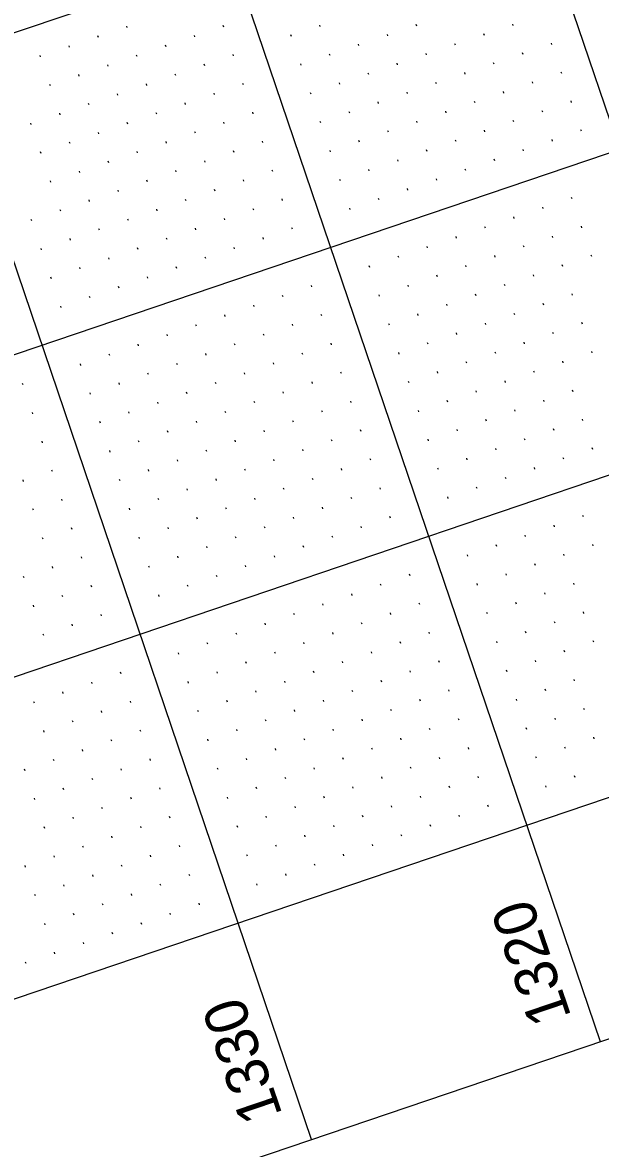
# Model space of a CAD drawing. Extents: x 2150318 to 2152065, y 143281 to 145371.
# Drawn here: x 2151453.5 to 2151548.2, y 143673.5 to 143858.1 of the extents above; entities that cross this region are included whole.
import ezdxf

# ---------------------------------------------------------------- set-up
doc = ezdxf.new("R2010")
doc.units = 0
for name, color, linetype in [('SHT_Plan_Profile_Sheet_Elev_Txt', 7, 'Continuous'), ('SHT_Profile_Grid_Major', 7, 'Continuous'), ('SHT_Profile_Grid_Minor', 7, 'Continuous'), ('SHT_Sheet_Border', 7, 'Continuous')]:
    doc.layers.add(name, color=color, linetype=linetype)

msp = doc.modelspace()

# ---------------------------------------------------------------- linework, layer by layer
at = {"layer": 'SHT_Profile_Grid_Major'}
for p, q in [((2151595.52, 143707.09), (2151089.53, 145198.6)), ((2151548.17, 143691.03), (2151042.18, 145182.54)), ((2151500.82, 143674.97), (2150994.83, 145166.47)), ((2151819.38, 143981.03), (2151345.88, 143820.4)), ((2151835.44, 143933.68), (2151361.94, 143773.05)), ((2151851.5, 143886.33), (2151378.01, 143725.7))]:
    msp.add_line(p, q, dxfattribs=at)
at = {"layer": 'SHT_Profile_Grid_Minor'}
for p, q in [((2151470.64, 143857.31), (2151470.56, 143857.55)), ((2151486.45, 143857.39), (2151486.37, 143857.63)), ((2151502.26, 143857.48), (2151502.18, 143857.71)), ((2151518.07, 143857.56), (2151517.99, 143857.8)), ((2151533.88, 143857.65), (2151533.8, 143857.88)), ((2151465.9, 143855.7), (2151465.82, 143855.94)), ((2151481.71, 143855.79), (2151481.63, 143856.02)), ((2151497.52, 143855.87), (2151497.44, 143856.11)), ((2151513.34, 143855.96), (2151513.26, 143856.19)), ((2151529.15, 143856.04), (2151529.07, 143856.28)), ((2151461.17, 143854.1), (2151461.09, 143854.33)), ((2151476.98, 143854.18), (2151476.9, 143854.42)), ((2151508.6, 143854.35), (2151508.52, 143854.59)), ((2151524.41, 143854.43), (2151524.33, 143854.67)), ((2151540.22, 143854.52), (2151540.14, 143854.75)), ((2151456.43, 143852.49), (2151456.35, 143852.73)), ((2151472.24, 143852.58), (2151472.16, 143852.81)), ((2151488.05, 143852.66), (2151487.97, 143852.9)), ((2151503.87, 143852.74), (2151503.79, 143852.98)), ((2151514.94, 143851.22), (2151514.86, 143851.46)), ((2151519.68, 143852.83), (2151519.6, 143853.06)), ((2151530.75, 143851.3), (2151530.67, 143851.54)), ((2151535.49, 143852.91), (2151535.41, 143853.15)), ((2151462.77, 143849.36), (2151462.69, 143849.6)), ((2151467.51, 143850.97), (2151467.43, 143851.21)), ((2151478.58, 143849.45), (2151478.5, 143849.68)), ((2151483.32, 143851.05), (2151483.24, 143851.29)), ((2151499.13, 143851.14), (2151499.05, 143851.37)), ((2151510.21, 143849.61), (2151510.13, 143849.85)), ((2151526.02, 143849.7), (2151525.94, 143849.94)), ((2151541.83, 143849.78), (2151541.75, 143850.02)), ((2151458.04, 143847.76), (2151457.96, 143847.99)), ((2151473.85, 143847.84), (2151473.77, 143848.08)), ((2151489.66, 143847.92), (2151489.58, 143848.16)), ((2151505.47, 143848.01), (2151505.39, 143848.25)), ((2151521.28, 143848.09), (2151521.2, 143848.33)), ((2151537.09, 143848.18), (2151537.01, 143848.41)), ((2151469.11, 143846.23), (2151469.03, 143846.47)), ((2151484.93, 143846.32), (2151484.85, 143846.55)), ((2151500.74, 143846.4), (2151500.66, 143846.64)), ((2151516.55, 143846.49), (2151516.47, 143846.72)), ((2151532.36, 143846.57), (2151532.28, 143846.81)), ((2151464.38, 143844.63), (2151464.3, 143844.86)), ((2151480.19, 143844.71), (2151480.11, 143844.95)), ((2151511.81, 143844.88), (2151511.73, 143845.12)), ((2151527.62, 143844.96), (2151527.54, 143845.2)), ((2151543.44, 143845.05), (2151543.36, 143845.28)), ((2151459.64, 143843.02), (2151459.56, 143843.26)), ((2151475.46, 143843.11), (2151475.38, 143843.34)), ((2151491.27, 143843.19), (2151491.19, 143843.43)), ((2151507.08, 143843.27), (2151507, 143843.51)), ((2151522.89, 143843.36), (2151522.81, 143843.59)), ((2151538.7, 143843.44), (2151538.62, 143843.68)), ((2151454.91, 143841.42), (2151454.83, 143841.65)), ((2151470.72, 143841.5), (2151470.64, 143841.74)), ((2151486.53, 143841.58), (2151486.45, 143841.82)), ((2151502.34, 143841.67), (2151502.26, 143841.9)), ((2151513.42, 143840.14), (2151513.34, 143840.38)), ((2151518.15, 143841.75), (2151518.07, 143841.99)), ((2151529.23, 143840.23), (2151529.15, 143840.47)), ((2151533.97, 143841.84), (2151533.89, 143842.07)), ((2151545.04, 143840.31), (2151544.96, 143840.55)), ((2151461.25, 143838.29), (2151461.17, 143838.52)), ((2151465.99, 143839.89), (2151465.91, 143840.13)), ((2151477.06, 143838.37), (2151476.98, 143838.61)), ((2151481.8, 143839.98), (2151481.72, 143840.21)), ((2151492.87, 143838.45), (2151492.79, 143838.69)), ((2151508.68, 143838.54), (2151508.6, 143838.78)), ((2151524.5, 143838.62), (2151524.42, 143838.86)), ((2151540.31, 143838.71), (2151540.23, 143838.94)), ((2151456.52, 143836.68), (2151456.44, 143836.92)), ((2151472.33, 143836.76), (2151472.25, 143837)), ((2151488.14, 143836.85), (2151488.06, 143837.08)), ((2151503.95, 143836.93), (2151503.87, 143837.17)), ((2151519.76, 143837.02), (2151519.68, 143837.25)), ((2151535.57, 143837.1), (2151535.49, 143837.34)), ((2151467.59, 143835.16), (2151467.51, 143835.39)), ((2151483.4, 143835.24), (2151483.32, 143835.48)), ((2151515.03, 143835.41), (2151514.95, 143835.65)), ((2151530.84, 143835.49), (2151530.76, 143835.73)), ((2151462.86, 143833.55), (2151462.78, 143833.79)), ((2151478.67, 143833.64), (2151478.59, 143833.87)), ((2151494.48, 143833.72), (2151494.4, 143833.96)), ((2151510.29, 143833.8), (2151510.21, 143834.04)), ((2151526.1, 143833.89), (2151526.02, 143834.12)), ((2151458.12, 143831.95), (2151458.04, 143832.18)), ((2151473.93, 143832.03), (2151473.85, 143832.27)), ((2151489.74, 143832.11), (2151489.66, 143832.35)), ((2151505.56, 143832.2), (2151505.48, 143832.43)), ((2151521.37, 143832.28), (2151521.29, 143832.52)), ((2151469.2, 143830.42), (2151469.12, 143830.66)), ((2151485.01, 143830.51), (2151484.93, 143830.74)), ((2151511.9, 143829.07), (2151511.82, 143829.31)), ((2151516.63, 143830.67), (2151516.55, 143830.91)), ((2151543.52, 143829.24), (2151543.44, 143829.47)), ((2151459.73, 143827.21), (2151459.65, 143827.45)), ((2151464.46, 143828.82), (2151464.38, 143829.05)), ((2151475.54, 143827.29), (2151475.46, 143827.53)), ((2151480.27, 143828.9), (2151480.19, 143829.14)), ((2151491.35, 143827.38), (2151491.27, 143827.62)), ((2151496.09, 143828.98), (2151496.01, 143829.22)), ((2151507.16, 143827.46), (2151507.08, 143827.7)), ((2151538.78, 143827.63), (2151538.7, 143827.87)), ((2151454.99, 143825.6), (2151454.91, 143825.84)), ((2151470.81, 143825.69), (2151470.72, 143825.92)), ((2151486.62, 143825.77), (2151486.54, 143826.01)), ((2151534.05, 143826.02), (2151533.97, 143826.26)), ((2151466.07, 143824.08), (2151465.99, 143824.32)), ((2151481.88, 143824.17), (2151481.8, 143824.4)), ((2151497.69, 143824.25), (2151497.61, 143824.49)), ((2151529.31, 143824.42), (2151529.23, 143824.65)), ((2151545.13, 143824.5), (2151545.05, 143824.74)), ((2151461.34, 143822.48), (2151461.25, 143822.71)), ((2151477.15, 143822.56), (2151477.07, 143822.8)), ((2151492.96, 143822.64), (2151492.88, 143822.88)), ((2151524.58, 143822.81), (2151524.5, 143823.05)), ((2151540.39, 143822.9), (2151540.31, 143823.13)), ((2151456.6, 143820.87), (2151456.52, 143821.11)), ((2151472.41, 143820.95), (2151472.33, 143821.19)), ((2151488.22, 143821.04), (2151488.14, 143821.27)), ((2151519.84, 143821.2), (2151519.76, 143821.44)), ((2151535.66, 143821.29), (2151535.58, 143821.53)), ((2151546.73, 143819.77), (2151546.65, 143820)), ((2151467.68, 143819.35), (2151467.6, 143819.58)), ((2151483.49, 143819.43), (2151483.41, 143819.67)), ((2151510.37, 143817.99), (2151510.29, 143818.23)), ((2151515.11, 143819.6), (2151515.03, 143819.84)), ((2151526.19, 143818.08), (2151526.11, 143818.31)), ((2151530.92, 143819.68), (2151530.84, 143819.92)), ((2151542, 143818.16), (2151541.92, 143818.4)), ((2151458.21, 143816.13), (2151458.13, 143816.37)), ((2151462.94, 143817.74), (2151462.86, 143817.98)), ((2151474.02, 143816.22), (2151473.94, 143816.45)), ((2151478.75, 143817.82), (2151478.67, 143818.06)), ((2151521.45, 143816.47), (2151521.37, 143816.71)), ((2151537.26, 143816.55), (2151537.18, 143816.79)), ((2151469.28, 143814.61), (2151469.2, 143814.85)), ((2151500.9, 143814.78), (2151500.82, 143815.02)), ((2151516.72, 143814.86), (2151516.64, 143815.1)), ((2151532.53, 143814.95), (2151532.45, 143815.18)), ((2151464.55, 143813.01), (2151464.47, 143813.24)), ((2151496.17, 143813.17), (2151496.09, 143813.41)), ((2151511.98, 143813.26), (2151511.9, 143813.49)), ((2151527.79, 143813.34), (2151527.71, 143813.58)), ((2151543.6, 143813.43), (2151543.52, 143813.66)), ((2151459.81, 143811.4), (2151459.73, 143811.64)), ((2151491.44, 143811.57), (2151491.35, 143811.8)), ((2151523.06, 143811.74), (2151522.98, 143811.97)), ((2151538.87, 143811.82), (2151538.79, 143812.06)), ((2151486.7, 143809.96), (2151486.62, 143810.2)), ((2151502.51, 143810.04), (2151502.43, 143810.28)), ((2151518.32, 143810.13), (2151518.24, 143810.37)), ((2151534.13, 143810.21), (2151534.05, 143810.45)), ((2151545.21, 143808.69), (2151545.13, 143808.93)), ((2151481.97, 143808.35), (2151481.88, 143808.59)), ((2151497.78, 143808.44), (2151497.7, 143808.68)), ((2151513.59, 143808.52), (2151513.51, 143808.76)), ((2151524.66, 143807), (2151524.58, 143807.24)), ((2151529.4, 143808.61), (2151529.32, 143808.84)), ((2151540.47, 143807.08), (2151540.39, 143807.32)), ((2151472.5, 143805.14), (2151472.42, 143805.38)), ((2151477.23, 143806.75), (2151477.15, 143806.98)), ((2151488.31, 143805.23), (2151488.23, 143805.46)), ((2151493.04, 143806.83), (2151492.96, 143807.07)), ((2151504.12, 143805.31), (2151504.04, 143805.55)), ((2151519.93, 143805.39), (2151519.85, 143805.63)), ((2151535.74, 143805.48), (2151535.66, 143805.71)), ((2151467.76, 143803.54), (2151467.68, 143803.77)), ((2151483.57, 143803.62), (2151483.49, 143803.86)), ((2151499.38, 143803.7), (2151499.3, 143803.94)), ((2151515.19, 143803.79), (2151515.11, 143804.02)), ((2151531.01, 143803.87), (2151530.92, 143804.11)), ((2151546.82, 143803.96), (2151546.74, 143804.19)), ((2151463.03, 143801.93), (2151462.95, 143802.17)), ((2151478.84, 143802.01), (2151478.76, 143802.25)), ((2151494.65, 143802.1), (2151494.57, 143802.33)), ((2151526.27, 143802.27), (2151526.19, 143802.5)), ((2151542.08, 143802.35), (2151542, 143802.59)), ((2151474.1, 143800.41), (2151474.02, 143800.64)), ((2151489.91, 143800.49), (2151489.83, 143800.73)), ((2151505.72, 143800.57), (2151505.64, 143800.81)), ((2151521.54, 143800.66), (2151521.45, 143800.9)), ((2151537.35, 143800.74), (2151537.27, 143800.98)), ((2151453.56, 143798.72), (2151453.48, 143798.95)), ((2151469.37, 143798.8), (2151469.29, 143799.04)), ((2151485.18, 143798.88), (2151485.1, 143799.12)), ((2151500.99, 143798.97), (2151500.91, 143799.21)), ((2151516.8, 143799.05), (2151516.72, 143799.29)), ((2151532.61, 143799.14), (2151532.53, 143799.37)), ((2151543.69, 143797.61), (2151543.61, 143797.85)), ((2151464.63, 143797.19), (2151464.55, 143797.43)), ((2151480.44, 143797.28), (2151480.36, 143797.51)), ((2151496.25, 143797.36), (2151496.17, 143797.6)), ((2151507.33, 143795.84), (2151507.25, 143796.08)), ((2151523.14, 143795.92), (2151523.06, 143796.16)), ((2151527.88, 143797.53), (2151527.8, 143797.77)), ((2151538.95, 143796.01), (2151538.87, 143796.24)), ((2151455.16, 143793.98), (2151455.08, 143794.22)), ((2151470.97, 143794.07), (2151470.89, 143794.3)), ((2151475.71, 143795.67), (2151475.63, 143795.91)), ((2151486.78, 143794.15), (2151486.7, 143794.39)), ((2151491.52, 143795.76), (2151491.44, 143795.99)), ((2151502.6, 143794.23), (2151502.51, 143794.47)), ((2151518.41, 143794.32), (2151518.33, 143794.55)), ((2151534.22, 143794.4), (2151534.14, 143794.64)), ((2151466.24, 143792.46), (2151466.16, 143792.7)), ((2151482.05, 143792.54), (2151481.97, 143792.78)), ((2151497.86, 143792.63), (2151497.78, 143792.86)), ((2151529.48, 143792.8), (2151529.4, 143793.03)), ((2151545.29, 143792.88), (2151545.21, 143793.12)), ((2151477.31, 143790.94), (2151477.23, 143791.17)), ((2151493.13, 143791.02), (2151493.05, 143791.26)), ((2151508.94, 143791.1), (2151508.86, 143791.34)), ((2151524.75, 143791.19), (2151524.67, 143791.43)), ((2151540.56, 143791.27), (2151540.48, 143791.51)), ((2151456.77, 143789.25), (2151456.69, 143789.48)), ((2151472.58, 143789.33), (2151472.5, 143789.57)), ((2151488.39, 143789.41), (2151488.31, 143789.65)), ((2151504.2, 143789.5), (2151504.12, 143789.74)), ((2151520.01, 143789.58), (2151519.93, 143789.82)), ((2151535.82, 143789.67), (2151535.74, 143789.9)), ((2151467.84, 143787.72), (2151467.76, 143787.96)), ((2151483.66, 143787.81), (2151483.58, 143788.05)), ((2151499.47, 143787.89), (2151499.39, 143788.13)), ((2151531.09, 143788.06), (2151531.01, 143788.3)), ((2151542.17, 143786.54), (2151542.08, 143786.77)), ((2151546.9, 143788.14), (2151546.82, 143788.38)), ((2151478.92, 143786.2), (2151478.84, 143786.44)), ((2151494.73, 143786.29), (2151494.65, 143786.52)), ((2151505.81, 143784.76), (2151505.73, 143785)), ((2151510.54, 143786.37), (2151510.46, 143786.61)), ((2151521.62, 143784.85), (2151521.54, 143785.08)), ((2151526.35, 143786.45), (2151526.27, 143786.69)), ((2151537.43, 143784.93), (2151537.35, 143785.17)), ((2151453.64, 143782.91), (2151453.56, 143783.14)), ((2151458.37, 143784.51), (2151458.29, 143784.75)), ((2151469.45, 143782.99), (2151469.37, 143783.23)), ((2151474.19, 143784.6), (2151474.11, 143784.83)), ((2151485.26, 143783.07), (2151485.18, 143783.31)), ((2151490, 143784.68), (2151489.92, 143784.92)), ((2151501.07, 143783.16), (2151500.99, 143783.39)), ((2151532.7, 143783.33), (2151532.62, 143783.56)), ((2151480.53, 143781.47), (2151480.45, 143781.7)), ((2151496.34, 143781.55), (2151496.26, 143781.79)), ((2151512.15, 143781.64), (2151512.07, 143781.87)), ((2151527.96, 143781.72), (2151527.88, 143781.96)), ((2151459.98, 143779.78), (2151459.9, 143780.01)), ((2151475.79, 143779.86), (2151475.71, 143780.1)), ((2151491.6, 143779.94), (2151491.52, 143780.18)), ((2151507.41, 143780.03), (2151507.33, 143780.27)), ((2151523.23, 143780.11), (2151523.15, 143780.35)), ((2151455.25, 143778.17), (2151455.17, 143778.41)), ((2151471.06, 143778.25), (2151470.98, 143778.49)), ((2151486.87, 143778.34), (2151486.79, 143778.58)), ((2151502.68, 143778.42), (2151502.6, 143778.66)), ((2151482.13, 143776.73), (2151482.05, 143776.97)), ((2151497.94, 143776.82), (2151497.86, 143777.05)), ((2151513.76, 143776.9), (2151513.68, 143777.14)), ((2151540.64, 143775.46), (2151540.56, 143775.7)), ((2151545.38, 143777.07), (2151545.3, 143777.3)), ((2151461.59, 143775.04), (2151461.51, 143775.28)), ((2151477.4, 143775.13), (2151477.32, 143775.36)), ((2151493.21, 143775.21), (2151493.13, 143775.45)), ((2151504.29, 143773.69), (2151504.21, 143773.92)), ((2151509.02, 143775.29), (2151508.94, 143775.53)), ((2151535.91, 143773.86), (2151535.83, 143774.09)), ((2151456.85, 143773.44), (2151456.77, 143773.67)), ((2151472.66, 143773.52), (2151472.58, 143773.76)), ((2151483.74, 143772), (2151483.66, 143772.23)), ((2151488.47, 143773.6), (2151488.39, 143773.84)), ((2151499.55, 143772.08), (2151499.47, 143772.32)), ((2151531.17, 143772.25), (2151531.09, 143772.49)), ((2151546.98, 143772.33), (2151546.9, 143772.57)), ((2151463.19, 143770.31), (2151463.11, 143770.54)), ((2151479, 143770.39), (2151478.92, 143770.63)), ((2151494.82, 143770.47), (2151494.74, 143770.71)), ((2151526.44, 143770.64), (2151526.36, 143770.88)), ((2151542.25, 143770.73), (2151542.17, 143770.96)), ((2151458.46, 143768.7), (2151458.38, 143768.94)), ((2151474.27, 143768.78), (2151474.19, 143769.02)), ((2151490.08, 143768.87), (2151490, 143769.11)), ((2151537.51, 143769.12), (2151537.43, 143769.36)), ((2151453.72, 143767.09), (2151453.64, 143767.33)), ((2151485.35, 143767.26), (2151485.27, 143767.5)), ((2151516.97, 143767.43), (2151516.89, 143767.67)), ((2151532.78, 143767.51), (2151532.7, 143767.75)), ((2151464.8, 143765.57), (2151464.72, 143765.81)), ((2151480.61, 143765.66), (2151480.53, 143765.89)), ((2151512.23, 143765.82), (2151512.15, 143766.06)), ((2151528.04, 143765.91), (2151527.96, 143766.14)), ((2151539.12, 143764.39), (2151539.04, 143764.62)), ((2151543.86, 143765.99), (2151543.78, 143766.23)), ((2151460.06, 143763.97), (2151459.98, 143764.2)), ((2151475.88, 143764.05), (2151475.8, 143764.29)), ((2151502.76, 143762.61), (2151502.68, 143762.85)), ((2151507.5, 143764.22), (2151507.42, 143764.45)), ((2151518.57, 143762.7), (2151518.49, 143762.93)), ((2151534.39, 143762.78), (2151534.31, 143763.02)), ((2151455.33, 143762.36), (2151455.25, 143762.6)), ((2151466.41, 143760.84), (2151466.33, 143761.07)), ((2151498.03, 143761), (2151497.95, 143761.24)), ((2151513.84, 143761.09), (2151513.76, 143761.33)), ((2151529.65, 143761.17), (2151529.57, 143761.41)), ((2151545.46, 143761.26), (2151545.38, 143761.49)), ((2151461.67, 143759.23), (2151461.59, 143759.47)), ((2151493.29, 143759.4), (2151493.21, 143759.64)), ((2151509.1, 143759.48), (2151509.02, 143759.72)), ((2151540.73, 143759.65), (2151540.65, 143759.89)), ((2151456.94, 143757.62), (2151456.86, 143757.86)), ((2151488.56, 143757.79), (2151488.48, 143758.03)), ((2151504.37, 143757.88), (2151504.29, 143758.11)), ((2151520.18, 143757.96), (2151520.1, 143758.2)), ((2151535.99, 143758.04), (2151535.91, 143758.28)), ((2151483.82, 143756.19), (2151483.74, 143756.42)), ((2151499.63, 143756.27), (2151499.55, 143756.51)), ((2151515.45, 143756.35), (2151515.37, 143756.59)), ((2151531.26, 143756.44), (2151531.18, 143756.67)), ((2151547.07, 143756.52), (2151546.99, 143756.76)), ((2151479.09, 143754.58), (2151479.01, 143754.82)), ((2151494.9, 143754.66), (2151494.82, 143754.9)), ((2151510.71, 143754.75), (2151510.63, 143754.98)), ((2151537.6, 143753.31), (2151537.52, 143753.55)), ((2151542.33, 143754.92), (2151542.25, 143755.15)), ((2151490.16, 143753.06), (2151490.08, 143753.29)), ((2151501.24, 143751.54), (2151501.16, 143751.77)), ((2151505.98, 143753.14), (2151505.9, 143753.38)), ((2151517.05, 143751.62), (2151516.97, 143751.86)), ((2151521.79, 143753.23), (2151521.71, 143753.46)), ((2151532.86, 143751.7), (2151532.78, 143751.94)), ((2151464.88, 143749.76), (2151464.8, 143750)), ((2151469.62, 143751.37), (2151469.54, 143751.6)), ((2151480.69, 143749.84), (2151480.61, 143750.08)), ((2151485.43, 143751.45), (2151485.35, 143751.69)), ((2151496.51, 143749.93), (2151496.43, 143750.17)), ((2151512.32, 143750.01), (2151512.24, 143750.25)), ((2151543.94, 143750.18), (2151543.86, 143750.42)), ((2151460.15, 143748.15), (2151460.07, 143748.39)), ((2151491.77, 143748.32), (2151491.69, 143748.56)), ((2151507.58, 143748.41), (2151507.5, 143748.64)), ((2151523.39, 143748.49), (2151523.31, 143748.73)), ((2151539.2, 143748.57), (2151539.12, 143748.81)), ((2151455.41, 143746.55), (2151455.33, 143746.78)), ((2151471.22, 143746.63), (2151471.14, 143746.87)), ((2151487.04, 143746.72), (2151486.96, 143746.95)), ((2151502.85, 143746.8), (2151502.77, 143747.04)), ((2151518.66, 143746.88), (2151518.58, 143747.12)), ((2151534.47, 143746.97), (2151534.39, 143747.2)), ((2151466.49, 143745.03), (2151466.41, 143745.26)), ((2151482.3, 143745.11), (2151482.22, 143745.35)), ((2151498.11, 143745.19), (2151498.03, 143745.43)), ((2151513.92, 143745.28), (2151513.84, 143745.51)), ((2151545.55, 143745.45), (2151545.47, 143745.68)), ((2151461.76, 143743.42), (2151461.67, 143743.66)), ((2151493.38, 143743.59), (2151493.3, 143743.82)), ((2151509.19, 143743.67), (2151509.11, 143743.91)), ((2151525, 143743.76), (2151524.92, 143743.99)), ((2151536.08, 143742.23), (2151536, 143742.47)), ((2151540.81, 143743.84), (2151540.73, 143744.08)), ((2151457.02, 143741.81), (2151456.94, 143742.05)), ((2151472.83, 143741.9), (2151472.75, 143742.13)), ((2151488.64, 143741.98), (2151488.56, 143742.22)), ((2151499.72, 143740.46), (2151499.64, 143740.7)), ((2151504.45, 143742.07), (2151504.37, 143742.3)), ((2151515.53, 143740.54), (2151515.45, 143740.78)), ((2151520.26, 143742.15), (2151520.18, 143742.39)), ((2151547.15, 143740.71), (2151547.07, 143740.95)), ((2151463.36, 143738.68), (2151463.28, 143738.92)), ((2151468.1, 143740.29), (2151468.02, 143740.53)), ((2151483.91, 143740.37), (2151483.83, 143740.61)), ((2151494.98, 143738.85), (2151494.9, 143739.09)), ((2151510.79, 143738.94), (2151510.71, 143739.17)), ((2151526.61, 143739.02), (2151526.53, 143739.26)), ((2151542.42, 143739.1), (2151542.34, 143739.34)), ((2151458.63, 143737.08), (2151458.55, 143737.31)), ((2151474.44, 143737.16), (2151474.36, 143737.4)), ((2151490.25, 143737.25), (2151490.17, 143737.48)), ((2151506.06, 143737.33), (2151505.98, 143737.57)), ((2151521.87, 143737.41), (2151521.79, 143737.65)), ((2151537.68, 143737.5), (2151537.6, 143737.73)), ((2151453.89, 143735.47), (2151453.81, 143735.71)), ((2151469.7, 143735.56), (2151469.62, 143735.79)), ((2151485.51, 143735.64), (2151485.43, 143735.88)), ((2151501.33, 143735.72), (2151501.24, 143735.96)), ((2151517.14, 143735.81), (2151517.06, 143736.04)), ((2151464.97, 143733.95), (2151464.89, 143734.19)), ((2151496.59, 143734.12), (2151496.51, 143734.35)), ((2151512.4, 143734.2), (2151512.32, 143734.44)), ((2151528.21, 143734.29), (2151528.13, 143734.52)), ((2151544.02, 143734.37), (2151543.94, 143734.61)), ((2151460.23, 143732.34), (2151460.15, 143732.58)), ((2151476.04, 143732.43), (2151475.96, 143732.66)), ((2151491.86, 143732.51), (2151491.77, 143732.75)), ((2151507.67, 143732.6), (2151507.59, 143732.83)), ((2151523.48, 143732.68), (2151523.4, 143732.92)), ((2151539.29, 143732.76), (2151539.21, 143733)), ((2151455.5, 143730.74), (2151455.42, 143730.97)), ((2151471.31, 143730.82), (2151471.23, 143731.06)), ((2151487.12, 143730.9), (2151487.04, 143731.14)), ((2151498.2, 143729.38), (2151498.12, 143729.62)), ((2151502.93, 143730.99), (2151502.85, 143731.23)), ((2151514.01, 143729.47), (2151513.93, 143729.7)), ((2151518.74, 143731.07), (2151518.66, 143731.31)), ((2151529.82, 143729.55), (2151529.74, 143729.79)), ((2151461.84, 143727.61), (2151461.76, 143727.85)), ((2151466.57, 143729.21), (2151466.49, 143729.45)), ((2151477.65, 143727.69), (2151477.57, 143727.93)), ((2151493.46, 143727.78), (2151493.38, 143728.01)), ((2151509.27, 143727.86), (2151509.19, 143728.1)), ((2151525.08, 143727.94), (2151525, 143728.18)), ((2151457.1, 143726), (2151457.02, 143726.24)), ((2151472.92, 143726.09), (2151472.83, 143726.32)), ((2151488.73, 143726.17), (2151488.65, 143726.41)), ((2151504.54, 143726.25), (2151504.46, 143726.49)), ((2151520.35, 143726.34), (2151520.27, 143726.57)), ((2151468.18, 143724.48), (2151468.1, 143724.72)), ((2151499.8, 143724.65), (2151499.72, 143724.88)), ((2151515.61, 143724.73), (2151515.53, 143724.97)), ((2151463.45, 143722.87), (2151463.37, 143723.11)), ((2151479.26, 143722.96), (2151479.18, 143723.19)), ((2151495.07, 143723.04), (2151494.99, 143723.28)), ((2151510.88, 143723.13), (2151510.8, 143723.36)), ((2151458.71, 143721.27), (2151458.63, 143721.5)), ((2151474.52, 143721.35), (2151474.44, 143721.59)), ((2151490.33, 143721.44), (2151490.25, 143721.67)), ((2151506.14, 143721.52), (2151506.06, 143721.76)), ((2151453.98, 143719.66), (2151453.9, 143719.9)), ((2151469.79, 143719.74), (2151469.71, 143719.98)), ((2151480.86, 143718.22), (2151480.78, 143718.46)), ((2151496.67, 143718.31), (2151496.59, 143718.54)), ((2151501.41, 143719.91), (2151501.33, 143720.15)), ((2151460.32, 143716.53), (2151460.24, 143716.77)), ((2151465.05, 143718.14), (2151464.97, 143718.38)), ((2151476.13, 143716.62), (2151476.05, 143716.85)), ((2151491.94, 143716.7), (2151491.86, 143716.94)), ((2151455.58, 143714.93), (2151455.5, 143715.16)), ((2151471.39, 143715.01), (2151471.31, 143715.25)), ((2151466.66, 143713.4), (2151466.58, 143713.64)), ((2151482.47, 143713.49), (2151482.39, 143713.72)), ((2151461.92, 143711.8), (2151461.84, 143712.03)), ((2151477.73, 143711.88), (2151477.65, 143712.12)), ((2151457.19, 143710.19), (2151457.11, 143710.43)), ((2151473, 143710.27), (2151472.92, 143710.51)), ((2151468.26, 143708.67), (2151468.18, 143708.91)), ((2151458.79, 143705.46), (2151458.71, 143705.69)), ((2151463.53, 143707.06), (2151463.45, 143707.3)), ((2151454.06, 143703.85), (2151453.98, 143704.09))]:
    msp.add_line(p, q, dxfattribs=at)
at = {"layer": 'SHT_Sheet_Border'}
msp.add_line((2151867.57, 143838.98), (2151394.07, 143678.35), dxfattribs=at)
msp.add_lwpolyline([(2150901.85, 143471.77), (2150395.86, 144963.28), (2151390.2, 145300.6), (2151896.19, 143809.09)], close=True, dxfattribs=at)

# ---------------------------------------------------------------- texts
at = {"layer": 'SHT_Plan_Profile_Sheet_Elev_Txt'}
for s, p in [('1320', (2151543.44, 143695.12)), ('1330', (2151496.1, 143679.06))]:
    msp.add_text(s, height=7, rotation=108.7393, dxfattribs=at).set_placement(p)

doc.saveas('drawing.dxf')
